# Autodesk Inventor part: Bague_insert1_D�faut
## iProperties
Created: 2011-01
Part Number: Bague_insert1_D�faut
Document SubType Name: Modeling
Designer: eric
Density: 1 g/cm^3
Mass: 31.5814 g
Surface Area: 118.004 cm^2
Volume: 31.5814 cm^3
Author: eric
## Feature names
1. Base1
